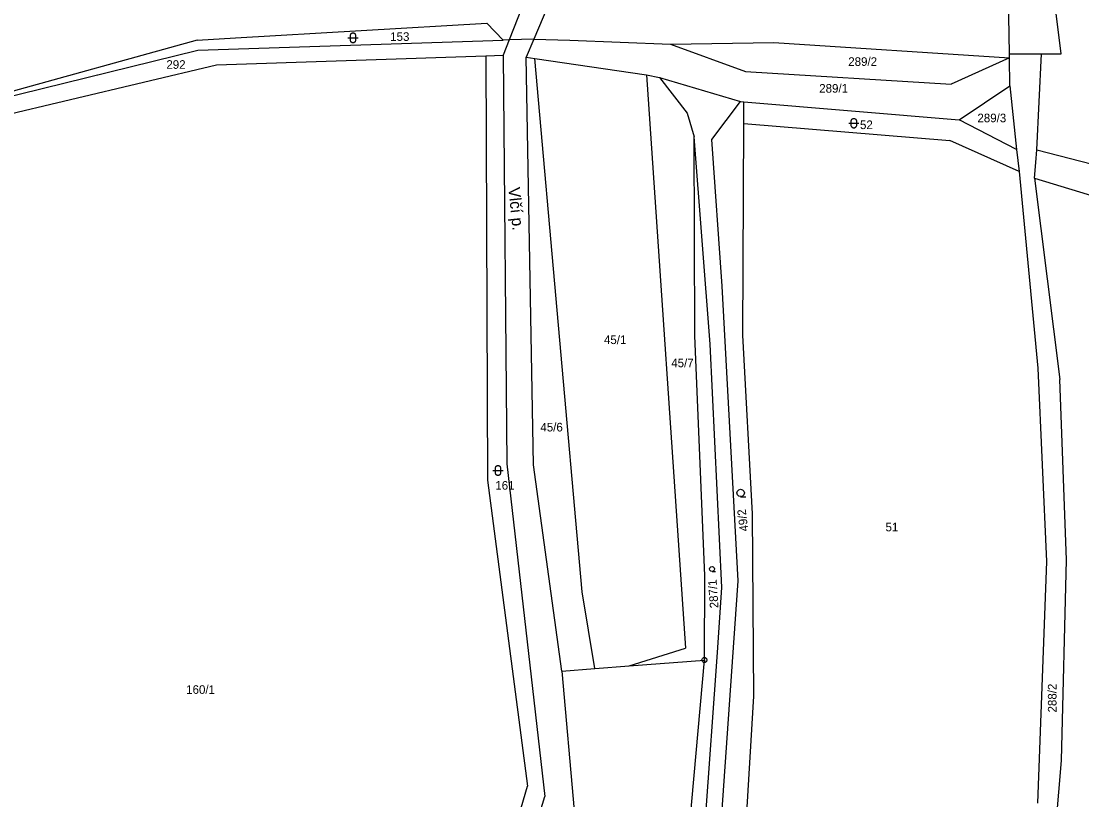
# Model space of a CAD drawing. Extents: x -779723 to -777378, y -1011169 to -1009297.
# Drawn here: x -779195.8 to -778986.4, y -1010034.3 to -1009880.5 of the extents above; entities that cross this region are included whole.
import ezdxf

# ---------------------------------------------------------------- set-up
doc = ezdxf.new("R2010")
doc.units = 0
for name, color, linetype in [('Default', 7, 'Continuous'), ('KN_HRANICE', 7, 'Continuous'), ('KN_KULTURY', 7, 'Continuous'), ('KN_PARCELY', 7, 'Continuous')]:
    doc.layers.add(name, color=color, linetype=linetype)

# ---------------------------------------------------------------- blocks, each defined once
blk = doc.blocks.new('304')
at = {"layer": 'Default'}
blk.add_lwpolyline([(0, 0), (-0.38, 0.1), (-0.65, 0.37), (-0.75, 0.74), (-0.65, 1.11), (-0.38, 1.38), (-0.01, 1.48), (0.36, 1.38), (0.63, 1.11), (0.73, 0.73), (0.63, 0.35), (0.36, 0.08), (-0.02, -0.02), (0.98, -0.02)], dxfattribs=at)
blk = doc.blocks.new('316')
at = {"layer": 'Default'}
for points in [[(-1, 1), (0.27, 1), (1, 1)], [(-0.5, 1.5), (-0.4, 1.79), (-0.15, 1.97), (0.16, 1.97), (0.41, 1.79), (0.51, 1.5), (0.51, 0.5), (0.41, 0.21), (0.16, 0.03), (-0.15, 0.03), (-0.4, 0.21), (-0.5, 0.5), (-0.5, 1.5)]]:
    blk.add_lwpolyline(points, dxfattribs=at)
blk = doc.blocks.new('105')
at = {"layer": 'Default'}
blk.add_line((-0.12, 0), (0.12, 0), dxfattribs=at)
blk.add_lwpolyline([(0.15, 0.48), (0.4, 0.3), (0.5, 0.01), (0.4, -0.28), (0.15, -0.46), (-0.16, -0.46), (-0.41, -0.28), (-0.51, 0.01), (-0.41, 0.3), (-0.16, 0.48), (0.15, 0.48)], dxfattribs=at)

msp = doc.modelspace()

# ---------------------------------------------------------------- linework, layer by layer
at = {"layer": 'KN_HRANICE'}
for p, q in [((-778990.51, -1009886.89), (-778995.32, -1009846.4)), ((-779085.09, -1009861.37), (-779094.6, -1009883.98)), ((-779090.96, -1009862.3), (-779099.45, -1009884.17)), ((-779000.69, -1009886.92), (-779001.1, -1009864.61)), ((-779153.46, -1009883.76), (-779103.85, -1009880.84)), ((-779100.65, -1009884.22), (-779103.85, -1009880.84)), ((-779161.05, -1009884.21), (-779228.01, -1009902.71)), ((-779161.05, -1009884.21), (-779153.46, -1009883.76)), ((-779160.94, -1009886.18), (-779100.65, -1009884.22)), ((-779099.45, -1009884.17), (-779100.65, -1009884.22)), ((-779099.45, -1009884.17), (-779100.62, -1009887.2)), ((-779094.6, -1009883.98), (-779099.45, -1009884.17)), ((-779094.6, -1009883.98), (-779096.11, -1009887.57)), ((-779094.6, -1009883.98), (-779087.51, -1009884.24)), ((-779087.51, -1009884.24), (-779067.61, -1009884.97)), ((-779067.61, -1009884.97), (-779047.2, -1009884.67)), ((-779047.2, -1009884.67), (-779000.66, -1009887.68)), ((-779228.01, -1009902.71), (-779160.94, -1009886.18)), ((-779067.61, -1009884.97), (-779052.83, -1009890.38)), ((-779157.23, -1009889.11), (-779104.09, -1009887.32)), ((-779104.09, -1009887.32), (-779100.62, -1009887.2)), ((-779104.09, -1009887.32), (-779103.74, -1009971.15)), ((-779100.62, -1009887.2), (-779099.92, -1009967.93)), ((-779096.11, -1009887.57), (-779094.38, -1009887.82)), ((-779094.66, -1009968.11), (-779096.11, -1009887.57)), ((-779085.07, -1009993.19), (-779094.38, -1009887.82)), ((-779094.38, -1009887.82), (-779072.34, -1009891.03)), ((-779000.66, -1009887.68), (-779012.19, -1009892.91)), ((-779000.69, -1009886.92), (-778994.39, -1009886.9)), ((-779000.66, -1009887.68), (-779000.69, -1009886.92)), ((-779000.59, -1009893.21), (-779000.66, -1009887.68)), ((-778995.28, -1009905.9), (-778994.39, -1009886.9)), ((-778994.39, -1009886.9), (-778990.51, -1009886.89)), ((-779229.16, -1009906.17), (-779157.23, -1009889.11)), ((-779072.34, -1009891.03), (-779064.62, -1010004.34)), ((-779072.34, -1009891.03), (-779069.8, -1009891.58)), ((-779052.83, -1009890.38), (-779012.19, -1009892.91)), ((-779069.8, -1009891.58), (-779064.32, -1009898.65)), ((-779069.8, -1009891.58), (-779053.8, -1009896.31)), ((-779010.63, -1009899.97), (-779000.59, -1009893.21)), ((-779000.59, -1009893.21), (-778999.33, -1009905.81)), ((-779059.45, -1009903.84), (-779053.8, -1009896.31)), ((-779053.8, -1009896.31), (-779053.14, -1009896.37)), ((-779053.15, -1009900.68), (-779053.14, -1009896.37)), ((-779053.14, -1009896.37), (-779010.63, -1009899.97)), ((-779064.32, -1009898.65), (-779062.96, -1009903.31)), ((-779053.3, -1009942.49), (-779053.15, -1009900.68)), ((-779053.15, -1009900.68), (-779012.48, -1009904.03)), ((-778999.33, -1009905.81), (-779010.63, -1009899.97)), ((-779059.75, -1009944.26), (-779062.96, -1009903.31)), ((-779062.79, -1009942.55), (-779062.96, -1009903.31)), ((-779057.44, -1009932.81), (-779059.45, -1009903.84)), ((-778998.76, -1009910.16), (-779012.48, -1009904.03)), ((-778999.33, -1009905.81), (-778998.76, -1009910.16)), ((-778995.48, -1009908.39), (-778995.28, -1009905.9)), ((-778995.28, -1009905.9), (-778982.29, -1009909.24)), ((-778995.73, -1009911.49), (-778995.48, -1009908.39)), ((-778998.76, -1009910.16), (-778995.06, -1009949.03)), ((-778995.73, -1009911.49), (-778990.76, -1009951.25)), ((-778995.73, -1009911.49), (-778981.54, -1009915.82)), ((-779054.27, -1009991.06), (-779057.44, -1009932.81)), ((-779060.86, -1009990.02), (-779062.79, -1009942.55)), ((-779051.39, -1009977.8), (-779053.3, -1009942.49)), ((-779057.48, -1009992.33), (-779059.75, -1009944.26)), ((-778995.06, -1009949.03), (-778993.39, -1009987.2)), ((-778989.44, -1009986.87), (-778990.76, -1009951.25)), ((-779099.92, -1009967.93), (-779092.42, -1010033.66)), ((-779089.05, -1010008.86), (-779094.66, -1009968.11)), ((-779103.74, -1009971.15), (-779095.87, -1010031.58)), ((-779051.15, -1010013.83), (-779051.39, -1009977.8)), ((-778993.39, -1009987.2), (-778995.17, -1010034.93)), ((-778990.39, -1010026.53), (-778989.44, -1009986.87)), ((-779060.91, -1010006.68), (-779060.86, -1009990.02)), ((-779058.05, -1010045.25), (-779054.27, -1009991.06)), ((-779082.54, -1010008.36), (-779085.07, -1009993.19)), ((-779058.32, -1010005.21), (-779057.48, -1009992.33)), ((-779075.8, -1010007.83), (-779064.62, -1010004.34)), ((-779061.16, -1010044.35), (-779058.32, -1010005.21)), ((-779082.54, -1010008.36), (-779075.8, -1010007.83)), ((-779075.8, -1010007.83), (-779060.91, -1010006.68)), ((-779064.44, -1010046.12), (-779060.91, -1010006.68)), ((-779089.05, -1010008.86), (-779082.54, -1010008.36)), ((-779089.05, -1010008.86), (-779086.6, -1010036.39)), ((-779054.9, -1010077.1), (-779051.15, -1010013.83)), ((-778993.67, -1010065.04), (-778990.39, -1010026.53)), ((-779110.38, -1010081.7), (-779095.87, -1010031.58)), ((-779107.64, -1010083.35), (-779092.42, -1010033.66))]:
    msp.add_line(p, q, dxfattribs=at)

# ---------------------------------------------------------------- block references
at = {"layer": 'KN_KULTURY'}
for name, p in [('316', (-779130.3, -1009884.76)), ('316', (-779031.42, -1009901.63)), ('316', (-779101.67, -1009970.24)), ('304', (-779053.75, -1009974.4))]:
    msp.add_blockref(name, p, dxfattribs=at)
at = {"layer": 'KN_KULTURY', "xscale": 0.67, "yscale": 0.67}
msp.add_blockref('304', (-779059.4, -1009989.18), dxfattribs=at)
at = {"layer": 'KN_PARCELY'}
msp.add_blockref('105', (-779060.91, -1010006.68), dxfattribs=at)

# ---------------------------------------------------------------- texts
for s, p in [('153', (-779122.95, -1009884.35)), ('292', (-779167.14, -1009889.87)), ('289/2', (-779032.52, -1009889.29)), ('289/1', (-779038.25, -1009894.58)), ('289/3', (-779007.02, -1009900.43)), ('52', (-779030.2, -1009901.78)), ('45/1', (-779080.75, -1009944.25)), ('45/7', (-779067.46, -1009948.83)), ('45/6', (-779093.3, -1009961.52)), ('161', (-779102.2, -1009973.02)), ('51', (-779025.16, -1009981.25)), ('160/1', (-779163.23, -1010013.36))]:
    msp.add_text(s, height=1.7, dxfattribs=at).set_placement(p)
for s, height, rotation, p in [('Vlčí p.', 2.3, 275.936, (-779099.64, -1009913.4)), ('49/2', 1.7, 96.944, (-779052.24, -1009981.17)), ('287/1', 1.7, 93.908, (-779058.13, -1009996.39)), ('288/2', 1.7, 90.012, (-778991.4, -1010017.04))]:
    msp.add_text(s, height=height, rotation=rotation, dxfattribs=at).set_placement(p)

doc.saveas('drawing.dxf')
